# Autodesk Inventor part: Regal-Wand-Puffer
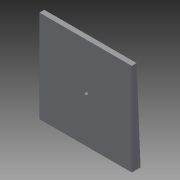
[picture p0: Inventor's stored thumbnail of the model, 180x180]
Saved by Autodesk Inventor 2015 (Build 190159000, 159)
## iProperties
Created: 2017-03
Part Number: Regal-Wand-Puffer
Material: Generisch
Document SubType Name: Modeling
Designer: Andreas
Density: 1 g/cm^3
Appearance: Vorgabe
Author: Andreas
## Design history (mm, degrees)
sketch "Skizze1"
  geometry: L1 (0, 0)-(5, 0); L2 (0, 0)-(0, -95); L3 (0, -95)-(9, -95); L4 (9, -95)-(5, 0)
  constraints: 8 end point, 1 horizontal, 1 perpendicular, 1 vertical
  dimensions: "d0" = 5 distance of L1.start L1.end; "d1" = 95 distance of L1.start L2.end; "d2" = 9 distance of L2.end L3.end
extrude "Extrusion1" new body sketch "Skizze1" distance "d3" = 95; taper "d4" = 0 deg
sketch "Skizze2"
  geometry: C1 r 2.1 at (47.5, 47.5); 2 further points
  constraints: 1 centre point, 1 coincident
  dimensions: "d5" = 4.2 diameter of C1
extrude "Extrusion2" cut sketch "Skizze2" stored distance "d6" = 95; taper "d7" = 0 deg
node "Volumenkörper1"
